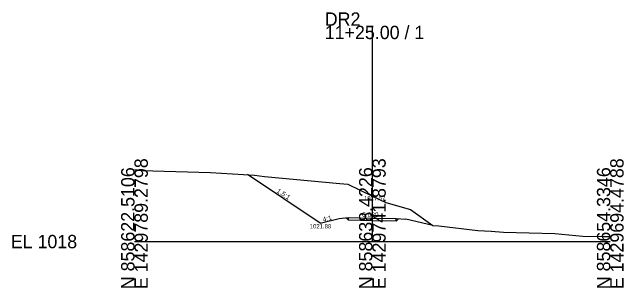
# Model space of a CAD drawing. Extents: x -26 to 103, y -10 to 3026.
# Drawn here: x -25.7 to 102.8, y 2490.3 to 2548.1 of the extents above; entities that cross this region are included whole.
import ezdxf

# ---------------------------------------------------------------- set-up
doc = ezdxf.new("R2010")
doc.units = 0
for name, color, linetype in [('Default', 7, 'Continuous'), ('Exist Cross Section Cell', 7, 'Continuous'), ('Exist XS Center Line Elevation Label', 7, 'Continuous'), ('Exist XS Ground Line', 7, 'Continuous'), ('Prop CMT Pvmt Surface', 7, 'Continuous'), ('Prop CMT Shld Paved Course 1', 7, 'Continuous'), ('Prop CMT Slope Grass', 7, 'Continuous'), ('Prop CMT Subgrade Earthwork', 7, 'Continuous'), ('Prop CMT Template Flag', 7, 'Continuous'), ('Prop XS SE Text', 7, 'Continuous'), ('Prop XS Side Slope Text', 7, 'Continuous')]:
    doc.layers.add(name, color=color, linetype=linetype)

msp = doc.modelspace()

# ---------------------------------------------------------------- linework, layer by layer
at = {"layer": 'Exist Cross Section Cell'}
for p, q in [((50, 2500), (50, 2545.31)), ((0, 2500), (50, 2500)), ((50, 2500), (100, 2500))]:
    msp.add_line(p, q, dxfattribs=at)
at = {"layer": 'Exist XS Ground Line'}
msp.add_lwpolyline([(0, 2515.1), (1.42, 2514.9), (15.99, 2514.5), (25.2, 2513.97), (27.31, 2513.69), (43.18, 2512.16), (44.83, 2512.04), (50, 2509.57), (52.82, 2508.22), (57.99, 2506.74), (62.7, 2503.4), (63.94, 2503.28), (72.19, 2502.33), (74.96, 2502.2), (77.55, 2502.01), (88.33, 2501.7), (94.22, 2501.11), (98.42, 2501.05), (100, 2501.06)], dxfattribs=at)
at = {"layer": 'Prop CMT Pvmt Surface'}
for p, q in [((45, 2505.04), (50, 2504.94)), ((50, 2504.94), (55, 2504.84))]:
    msp.add_line(p, q, dxfattribs=at)
at = {"layer": 'Prop CMT Shld Paved Course 1'}
for points in [[(45, 2504.49), (45, 2505.04)], [(55, 2504.29), (55, 2504.84)]]:
    msp.add_lwpolyline(points, dxfattribs=at)
at = {"layer": 'Prop CMT Slope Grass'}
for p, q in [((39, 2503.88), (23.73, 2514.06)), ((39, 2503.88), (43, 2504.88)), ((43, 2504.88), (45, 2505.04)), ((55, 2504.84), (57, 2504.68)), ((62.7, 2503.4), (57, 2504.68))]:
    msp.add_line(p, q, dxfattribs=at)
at = {"layer": 'Prop CMT Subgrade Earthwork'}
for points in [[(45, 2504.49), (44.5, 2505)], [(55, 2504.29), (55.5, 2504.8)]]:
    msp.add_lwpolyline(points, dxfattribs=at)
at = {"layer": 'Prop CMT Template Flag'}
for p, q in [((50, 2504.39), (45, 2504.49)), ((55, 2504.29), (50, 2504.39))]:
    msp.add_line(p, q, dxfattribs=at)

# ---------------------------------------------------------------- texts
at = {"layer": 'Default'}
msp.add_text('1021.88', height=0.9, dxfattribs=at).set_placement((36.85, 2502.77))
at = {"layer": 'Exist Cross Section Cell'}
for s, p in [('DR2', (40, 2545.31)), ('11+25.00 / 1', (40, 2542.51)), ('EL 1018', (-26, 2498.6))]:
    msp.add_text(s, height=2.8, dxfattribs=at).set_placement(p)
for s, p in [('E 1429789.2798', (2.8, 2490)), ('E 1429741.8793', (52.8, 2490)), ('E 1429694.4788', (102.8, 2490)), ('N 858622.5106', (0, 2490)), ('N 858638.4226', (50, 2490)), ('N 858654.3346', (100, 2490))]:
    msp.add_text(s, height=2.8, rotation=90, dxfattribs=at).set_placement(p)
at = {"layer": 'Exist XS Center Line Elevation Label'}
msp.add_text('1027.57', height=0.9, dxfattribs=at).set_placement((48.25, 2508.67))
at = {"layer": 'Prop XS SE Text'}
msp.add_text('0.020', height=1, rotation=358.8542, dxfattribs=at).set_placement((47.84, 2505.19))
at = {"layer": 'Prop XS Side Slope Text'}
for s, rotation, p in [('1.5:1', 326.3099, (29.78, 2510.42)), ('4:1', 14.0362, (39.69, 2504.12))]:
    msp.add_text(s, height=1, rotation=rotation, dxfattribs=at).set_placement(p)

doc.saveas('drawing.dxf')
